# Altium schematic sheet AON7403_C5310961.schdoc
size 127 x 101 mm
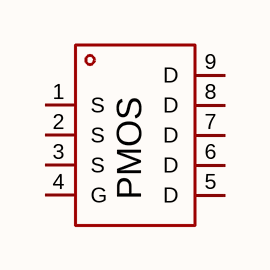
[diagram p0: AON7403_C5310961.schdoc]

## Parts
Q?  aon7403_c5310961  [DFN-8_L3.0-W3.0-P0.65-BL]  (value not drawn)

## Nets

Not connected (* = marked no-connect by the designer): Q? 1(S) 2(S) 3(S) 4(G) 5(D) 6(D) 7(D) 8(D) 9(D)

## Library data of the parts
Q? = aon7403_c5310961: 数量:1个P沟道;漏源电压(Vdss):30V;连续漏极电流(Id):50A;导通电阻(RDS(on)):8mΩ@10V;耗散功率(Pd):38W;阈值电压(Vgs(th)):1.2V;; Manufacturer: TECH PUBLIC(台舟); AddInBom: yes; ModelId: 8b850663669847e9b39b8fc804d68d4b; ModelName: DFN-8_L3.0-W3.0-H0.7-P0.65; ModelTransform: 118.8974,118.11,0,90,0,0,0,0,0; Number: 1个P沟道; Drain to Source Voltage: 30V; Current - Continuous Drain(Id): 50A; Pd - Power Dissipation: 38W; Gate Threshold Voltage (Vgs(th)): 1.2V; Gate Charge(Qg): 30nC@15V; Input Capacitance(Ciss): 3.448nF; Reverse Transfer Capacitance (Crss@Vds): 421pF; Type: P沟道; Output Capacitance(Coss): 508pF; Vgs: ±20V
